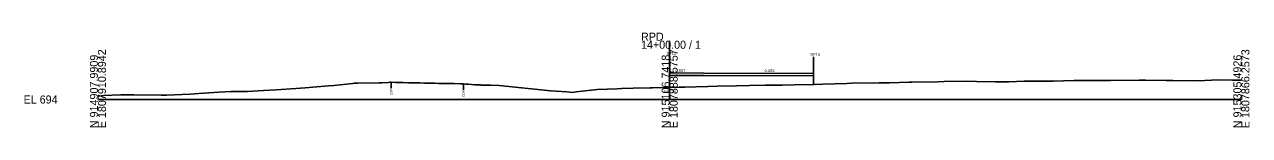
# Model space of a CAD drawing. Extents: x -26 to 403, y -10 to 8517.
# Drawn here: x -25.7 to 402.8, y 7990.3 to 8023.3 of the extents above; entities that cross this region are included whole.
import ezdxf

# ---------------------------------------------------------------- set-up
doc = ezdxf.new("R2010")
doc.units = 0
for name, color, linetype in [('Exist Cross Section Cell', 7, 'Continuous'), ('Exist XS Center Line Elevation Label', 7, 'Continuous'), ('Exist XS Ground Line', 7, 'Continuous'), ('Old_Level_10', 7, 'Continuous'), ('Prop XS Earthwork Shape', 7, 'Continuous'), ('Prop XS Finish Grade Pavement', 7, 'Continuous'), ('Prop XS SE Text', 7, 'Continuous'), ('Prop XS Subgrade Earthwork', 7, 'Continuous')]:
    doc.layers.add(name, color=color, linetype=linetype)

msp = doc.modelspace()

# ---------------------------------------------------------------- linework, layer by layer
at = {"layer": 'Exist Cross Section Cell'}
for p, q in [((200, 8000), (200, 8020.47)), ((0, 8000), (200, 8000)), ((200, 8000), (400, 8000))]:
    msp.add_line(p, q, dxfattribs=at)
at = {"layer": 'Exist XS Ground Line'}
msp.add_lwpolyline([(0, 8001.15), (1.26, 8001.25), (2.02, 8001.38), (8.01, 8001.58), (12.08, 8001.67), (12.6, 8001.68), (22.15, 8001.48), (23.94, 8001.54), (32.21, 8001.9), (35.27, 8002.04), (42.27, 8002.56), (46.61, 8002.76), (52.34, 8002.82), (57.94, 8003.08), (62.4, 8003.35), (69.28, 8003.84), (72.46, 8004.01), (80.61, 8004.72), (82.52, 8004.88), (89.2, 8005.62), (89.69, 8005.67), (90.83, 8005.7), (98.35, 8005.83), (99.26, 8005.85), (101.6, 8005.95), (102.16, 8005.98), (102.57, 8005.99), (104.11, 8005.97), (104.58, 8005.96), (106.63, 8005.91), (108.68, 8005.84), (109.14, 8005.83), (109.72, 8005.82), (111.66, 8005.77), (112.56, 8005.75), (114.18, 8005.72), (115.39, 8005.69), (116.69, 8005.67), (117.73, 8005.65), (119.21, 8005.63), (119.99, 8005.62), (121.72, 8005.58), (123.89, 8005.53), (124.51, 8005.52), (126.78, 8005.45), (127.84, 8005.43), (128.75, 8005.39), (129.56, 8005.35), (131.79, 8005.16), (133.81, 8005.05), (134.13, 8005.04), (135.66, 8005.01), (136.28, 8004.99), (136.96, 8004.98), (137.4, 8004.97), (140.38, 8004.89), (158.45, 8003.06), (164.06, 8002.65), (166.08, 8002.48), (167.28, 8002.62), (174.65, 8003.47), (181.66, 8003.74), (183.15, 8003.8), (187.24, 8003.91), (193.22, 8004.06), (193.97, 8004.08), (200, 8004.23), (203.28, 8004.31), (205.31, 8004.34), (213.34, 8004.56), (216.64, 8004.67), (223.4, 8004.79), (227.98, 8004.82), (233.47, 8004.94), (239.32, 8005.01), (243.53, 8005.09), (250.65, 8005.28), (253.59, 8005.32), (261.99, 8005.6), (263.66, 8005.69), (273.32, 8005.76), (273.72, 8005.77), (276.85, 8005.84), (283.78, 8006.01), (284.66, 8006.05), (293.84, 8006.21), (295.99, 8006.25), (303.91, 8006.37), (307.33, 8006.24), (313.97, 8006.19), (318.67, 8006.18), (324.03, 8006.33), (330, 8006.33), (334.1, 8006.34), (341.34, 8006.67), (344.16, 8006.64), (352.67, 8006.67), (354.22, 8006.67), (364.28, 8006.78), (366.46, 8006.75), (373.71, 8006.57), (375.99, 8006.57), (384.99, 8006.51), (391.71, 8006.82), (396.91, 8006.75), (400, 8006.7)], dxfattribs=at)
at = {"layer": 'Old_Level_10'}
for p, q in [((200, 8009.31), (200, 8015.26)), ((250.31, 8009.11), (250.31, 8014.89)), ((102.57, 8005.99), (102.57, 8003.94)), ((127.84, 8005.43), (127.84, 8003.38))]:
    msp.add_line(p, q, dxfattribs=at)
at = {"layer": 'Prop XS Earthwork Shape'}
for points in [[(233.47, 8004.94), (239.32, 8005.01), (243.53, 8005.09), (250.3, 8005.27), (250.3, 8008.19), (211.98, 8008.3), (199.98, 8008.39), (199.98, 8004.23), (200, 8004.23), (203.28, 8004.31), (205.31, 8004.34), (213.34, 8004.56), (216.64, 8004.67), (223.4, 8004.79), (227.98, 8004.82)], [(243.53, 8005.09), (250.3, 8005.27), (250.3, 8008.19), (211.98, 8008.3), (199.98, 8008.39), (199.98, 8004.23), (200, 8004.23), (203.28, 8004.31), (205.31, 8004.34), (213.34, 8004.56), (216.64, 8004.67), (223.4, 8004.79), (227.98, 8004.82), (233.47, 8004.94), (239.32, 8005.01)]]:
    msp.add_lwpolyline(points, close=True, dxfattribs=at)
at = {"layer": 'Prop XS Finish Grade Pavement'}
for p, q in [((200, 8009.31), (212, 8009.22)), ((200, 8008.39), (200, 8009.31)), ((212, 8009.22), (250.31, 8009.11)), ((250.31, 8009.11), (250.31, 8008.19))]:
    msp.add_line(p, q, dxfattribs=at)
at = {"layer": 'Prop XS Subgrade Earthwork'}
for p, q in [((199.98, 8008.39), (211.98, 8008.3)), ((199.98, 8004.23), (199.98, 8008.39)), ((211.98, 8008.3), (250.3, 8008.19)), ((250.3, 8008.19), (250.3, 8005.28))]:
    msp.add_line(p, q, dxfattribs=at)

# ---------------------------------------------------------------- texts
at = {"layer": 'Exist Cross Section Cell'}
for s, p in [('RPD', (190, 8020.47)), ('14+00.00 / 1', (190, 8017.67)), ('EL 694', (-26, 7998.6))]:
    msp.add_text(s, height=2.8, dxfattribs=at).set_placement(p)
for s, p in [('N 914907.9909', (0, 7990)), ('E 1807910.8942', (2.8, 7990)), ('N 915106.7418', (200, 7990)), ('E 1807888.5757', (202.8, 7990)), ('N 915305.4926', (400, 7990)), ('E 1807866.2573', (402.8, 7990))]:
    msp.add_text(s, height=2.8, rotation=90, dxfattribs=at).set_placement(p)
at = {"layer": 'Exist XS Center Line Elevation Label'}
msp.add_text('698.23', height=1, dxfattribs=at).set_placement((197.88, 8002.23))
at = {"layer": 'Old_Level_10'}
for s, p in [('SP12', (198.88, 8015.58)), ('SP14', (249.2, 8015.21))]:
    msp.add_text(s, height=1, dxfattribs=at).set_placement(p)
for p in [(102.97, 8001.55), (128.23, 8000.98)]:
    msp.add_text('EOP', height=0.787, rotation=90, dxfattribs=at).set_placement(p)
at = {"layer": 'Prop XS SE Text'}
for s, rotation, p in [('0.007', 359.5926, (202.03, 8009.59)), ('0.003', 359.5739, (233.2, 8009.57))]:
    msp.add_text(s, height=1, rotation=rotation, dxfattribs=at).set_placement(p)

doc.saveas('drawing.dxf')
